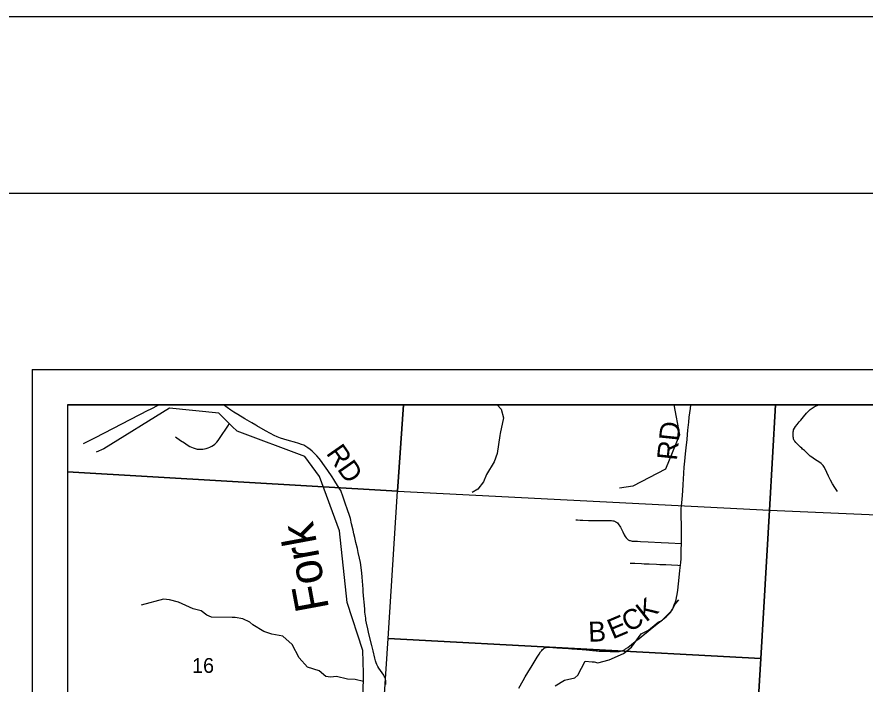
# Model space of a CAD drawing. Extents: x 21.4 to 65.3, y 4 to 26.
# Drawn here: x 23.404 to 25.81, y 24.062 to 25.954 of the extents above; entities that cross this region are included whole.
import ezdxf

# ---------------------------------------------------------------- set-up
doc = ezdxf.new("R2010")
doc.units = 0
for name, color, linetype in [('Default', 7, 'Continuous'), ('GM_X_County_Road', 7, 'Continuous'), ('GM_X_County_Road_Text', 7, 'Continuous'), ('GM_X_Minor_River', 7, 'Continuous'), ('GM_X_Minor_River_Text', 7, 'Continuous'), ('GM_X_Section', 7, 'Continuous'), ('GM_X_Section_Text', 7, 'Continuous'), ('GM_X_Township_Road', 7, 'Continuous'), ('GM_X_Township_Road_Text', 7, 'Continuous'), ('SH_Border', 7, 'Continuous'), ('SH_Cut_Line', 7, 'Continuous'), ('SH_Data', 7, 'Continuous')]:
    doc.layers.add(name, color=color, linetype=linetype)

msp = doc.modelspace()

# ---------------------------------------------------------------- linework, layer by layer
at = {"layer": 'Default'}
for points in [[(24.5002, 24.8542), (23.5473, 24.8542), (23.5473, 24.6641), (24.4839, 24.6087)], [(25.5568, 24.8542), (24.5002, 24.8542), (24.4839, 24.6087), (25.5389, 24.555)], [(26.6018, 24.8542), (25.5568, 24.8542), (25.5389, 24.555), (26.5825, 24.5101)], [(23.5473, 24.6641), (23.5473, 23.6293), (23.8211, 23.6164), (24.4175, 23.5863), (24.4178, 23.5899), (24.4301, 23.7749), (24.457, 24.1912), (24.4839, 24.6087)]]:
    msp.add_lwpolyline(points, close=True, dxfattribs=at)
msp.add_lwpolyline([(26.3906, 21.3613), (26.4573, 22.45), (26.4915, 22.9722), (26.4968, 23.0532), (26.5076, 23.2181), (26.5201, 23.4302), (26.5253, 23.5099), (26.571, 24.2838), (26.5714, 24.2916), (26.5716, 24.3007), (26.5721, 24.3116), (26.5728, 24.3278), (26.5729, 24.3421), (26.5729, 24.3464), (26.5731, 24.3575), (26.5731, 24.358), (26.5731, 24.3616), (26.5731, 24.3659), (26.5732, 24.3694), (26.5734, 24.3737), (26.5741, 24.3781), (26.6018, 24.8542), (23.5473, 24.8542), (23.5473, 20.5568)], dxfattribs=at)
at = {"layer": 'GM_X_County_Road'}
msp.add_lwpolyline([(24.4506, 24.0605), (24.4504, 24.071), (24.45, 24.0737), (24.4494, 24.0764), (24.4485, 24.0791), (24.4476, 24.0811), (24.4459, 24.0845), (24.4444, 24.0874), (24.4403, 24.094), (24.4355, 24.1006), (24.4311, 24.1066), (24.4278, 24.1117), (24.425, 24.1172), (24.4229, 24.1223), (24.4209, 24.1281), (24.419, 24.1353), (24.4145, 24.1565), (24.4128, 24.1638), (24.411, 24.1717), (24.4027, 24.2042), (24.3993, 24.2181), (24.3957, 24.235), (24.3942, 24.2429), (24.3934, 24.2484), (24.3913, 24.2663), (24.3908, 24.2731), (24.3897, 24.286), (24.3876, 24.312), (24.3865, 24.3243), (24.386, 24.3304), (24.385, 24.343), (24.3843, 24.3528), (24.3834, 24.3658), (24.3825, 24.3764), (24.3806, 24.3925), (24.3784, 24.4066), (24.376, 24.4194), (24.3724, 24.4352), (24.3699, 24.4461), (24.3658, 24.463), (24.3624, 24.4775), (24.3601, 24.4878), (24.3577, 24.4981), (24.3535, 24.5163), (24.3498, 24.5314), (24.3472, 24.5403), (24.342, 24.5557), (24.3354, 24.575), (24.328, 24.5975), (24.325, 24.6057), (24.3225, 24.6107), (24.3204, 24.6146), (24.3157, 24.6226), (24.3089, 24.6331), (24.303, 24.6419), (24.2979, 24.6496), (24.2857, 24.6677), (24.2719, 24.6875), (24.2676, 24.6936), (24.2615, 24.7015), (24.2549, 24.709), (24.2489, 24.7153), (24.2417, 24.7223), (24.2356, 24.7276), (24.2296, 24.7321), (24.2238, 24.7359), (24.2176, 24.7391), (24.2113, 24.7417), (24.2036, 24.7443), (24.191, 24.748), (24.1772, 24.7518), (24.1611, 24.7565), (24.1512, 24.7598), (24.1425, 24.7631), (24.1335, 24.7672), (24.123, 24.7725), (24.109, 24.7804), (24.0844, 24.7946), (24.0815, 24.7962), (24.0702, 24.8027), (24.0499, 24.8147), (24.0301, 24.8264), (24.0191, 24.8333), (24.0108, 24.8388), (24.0007, 24.846), (23.9924, 24.8524), (23.9903, 24.8542)], dxfattribs=at)
at = {"layer": 'GM_X_Minor_River'}
for points in [[(24.521, 23.3563), (24.5022, 23.4691), (24.5165, 23.5341), (24.5149, 23.6613), (24.4719, 23.7265), (24.4054, 23.7901), (24.406, 23.8584), (24.3844, 23.9087), (24.3873, 24.0927), (24.385, 24.1568), (24.3406, 24.2931), (24.319, 24.497), (24.2627, 24.6502), (24.2202, 24.7075), (24.0286, 24.7795), (24.0144, 24.7922), (23.9767, 24.8306), (23.8365, 24.8445), (23.6501, 24.729), (23.6289, 24.7193)], [(24.7662, 24.8542), (24.7782, 24.842), (24.7842, 24.8169), (24.7747, 24.7724), (24.774, 24.7671), (24.7668, 24.7157), (24.758, 24.6918), (24.736, 24.6564), (24.7277, 24.6359), (24.7114, 24.6145), (24.6958, 24.605)], [(25.2681, 24.8542), (25.2842, 24.769), (25.2441, 24.6715), (25.1513, 24.6236), (25.1138, 24.6176)], [(24.387, 24.0692), (24.3632, 24.0744), (24.342, 24.0759), (24.3109, 24.0831), (24.2931, 24.0819), (24.2806, 24.0834), (24.2609, 24.0994), (24.2279, 24.11), (24.2048, 24.1366), (24.1847, 24.1745), (24.1582, 24.1977), (24.1267, 24.203), (24.1043, 24.2113), (24.0733, 24.2295), (24.0642, 24.2379), (24.0448, 24.2466), (24.0229, 24.2508), (24.0145, 24.2508), (23.9561, 24.2518), (23.9425, 24.2575), (23.9266, 24.2693), (23.9042, 24.2757), (23.8625, 24.2943), (23.8368, 24.3011), (23.8197, 24.3026), (23.7564, 24.2855)], [(24.9311, 24.0564), (24.958, 24.0731), (24.9872, 24.08), (24.9951, 24.0872), (25.016, 24.1272), (25.0361, 24.1249), (25.0414, 24.1245), (25.0524, 24.1223), (25.0842, 24.1303), (25.1248, 24.1482), (25.1479, 24.1668), (25.1756, 24.2041), (25.1957, 24.2148), (25.2238, 24.2376), (25.234, 24.2422), (25.2628, 24.2711), (25.2715, 24.2886), (25.2818, 24.3004)]]:
    msp.add_lwpolyline(points, dxfattribs=at)
at = {"layer": 'GM_X_Section'}
for points in [[(24.4839, 24.6087), (25.5389, 24.555), (25.5145, 24.1345), (24.457, 24.1912)], [(26.5825, 24.5101), (26.5198, 23.4854), (25.4788, 23.5287), (25.4893, 23.7114), (25.5145, 24.1345), (25.5389, 24.555)], [(25.5145, 24.1345), (25.4893, 23.7114), (24.4301, 23.7749), (24.457, 24.1912)]]:
    msp.add_lwpolyline(points, close=True, dxfattribs=at)
at = {"layer": 'GM_X_Township_Road'}
for points in [[(23.5926, 24.7441), (23.6269, 24.761), (23.7765, 24.8386), (23.7826, 24.8417), (23.8064, 24.8538), (23.8072, 24.8542)], [(25.2355, 24.2439), (25.2379, 24.2457), (25.2462, 24.2522), (25.2484, 24.2543), (25.252, 24.2578), (25.2549, 24.2609), (25.2581, 24.2646), (25.2613, 24.2694), (25.2637, 24.2745), (25.2656, 24.2784), (25.2691, 24.2867), (25.2723, 24.295), (25.2741, 24.3006), (25.2758, 24.3072), (25.2775, 24.3163), (25.2791, 24.328), (25.2812, 24.3459), (25.285, 24.3835), (25.286, 24.3921), (25.2865, 24.3983), (25.2874, 24.4077), (25.2882, 24.4161), (25.2886, 24.4223), (25.2888, 24.4291), (25.289, 24.4428), (25.2893, 24.4602), (25.2895, 24.4788), (25.2895, 24.4962), (25.2892, 24.5154), (25.2887, 24.5353), (25.2887, 24.5508), (25.289, 24.5595), (25.2895, 24.567), (25.2911, 24.5856), (25.2935, 24.6103), (25.2946, 24.6276), (25.2952, 24.6431), (25.297, 24.6769), (25.2986, 24.6943), (25.3009, 24.715), (25.3027, 24.7316), (25.3054, 24.7557), (25.3067, 24.7699), (25.3079, 24.7823), (25.3101, 24.8052), (25.3117, 24.8194), (25.3132, 24.8317), (25.3147, 24.8434), (25.3162, 24.8542)], [(25.7319, 24.608), (25.7282, 24.6135), (25.7245, 24.6193), (25.7184, 24.6298), (25.7124, 24.6406), (25.7069, 24.6512), (25.7016, 24.6623), (25.6956, 24.676), (25.6938, 24.6792), (25.692, 24.6817), (25.6891, 24.6849), (25.6863, 24.6873), (25.6822, 24.6902), (25.6675, 24.6994), (25.663, 24.7025), (25.6593, 24.7051), (25.6549, 24.7085), (25.6503, 24.7126), (25.6452, 24.7176), (25.6384, 24.724), (25.6357, 24.7265), (25.6334, 24.7286), (25.6311, 24.7308), (25.6276, 24.7343), (25.6176, 24.7435), (25.6137, 24.7474), (25.6109, 24.7508), (25.6096, 24.7529), (25.6086, 24.755), (25.6079, 24.7572), (25.6071, 24.7608), (25.6068, 24.763), (25.6064, 24.7666), (25.6062, 24.7703), (25.6061, 24.7739), (25.6064, 24.7772), (25.607, 24.7802), (25.6079, 24.7827), (25.6103, 24.7875), (25.6131, 24.7921), (25.6174, 24.798), (25.6236, 24.8057), (25.6279, 24.8109), (25.636, 24.8202), (25.6448, 24.83), (25.6512, 24.8367), (25.6552, 24.8405), (25.6606, 24.8448), (25.6659, 24.848), (25.6714, 24.8508), (25.6792, 24.8542)], [(23.8534, 24.763), (23.8682, 24.7531), (23.8787, 24.7459), (23.8865, 24.7408), (23.8945, 24.7359), (23.8989, 24.7335), (23.9036, 24.7316), (23.9096, 24.7298), (23.9152, 24.7286), (23.9202, 24.728), (23.9259, 24.7279), (23.9315, 24.7283), (23.9359, 24.7289), (23.9408, 24.73), (23.9462, 24.7316), (23.9514, 24.7337), (23.9565, 24.7363), (23.9613, 24.7393), (23.9653, 24.7423), (23.9682, 24.7448), (23.9712, 24.748), (23.9747, 24.7524), (23.9808, 24.7611), (24.0024, 24.7937), (24.007, 24.8008)], [(24.9894, 24.5282), (24.9944, 24.5276), (25.0018, 24.527), (25.0092, 24.5267), (25.0258, 24.526), (25.06, 24.5257), (25.071, 24.5257), (25.0908, 24.5255), (25.095, 24.5249), (25.0974, 24.5245), (25.0996, 24.5238), (25.1011, 24.5231), (25.1025, 24.5223), (25.1051, 24.5208), (25.1075, 24.5189), (25.1096, 24.5167), (25.1122, 24.5133), (25.1144, 24.51), (25.1165, 24.5067), (25.1185, 24.5029), (25.1228, 24.4939), (25.1272, 24.485), (25.13, 24.4801), (25.1322, 24.477), (25.1342, 24.4746), (25.1371, 24.472), (25.1387, 24.471), (25.1403, 24.47), (25.1421, 24.4693), (25.1439, 24.4687), (25.147, 24.468), (25.15, 24.4674), (25.1543, 24.4671), (25.1643, 24.4668), (25.1736, 24.4664), (25.1953, 24.4654), (25.2318, 24.4638), (25.2529, 24.4628), (25.2893, 24.4602)], [(25.1438, 24.4051), (25.1569, 24.4045), (25.1761, 24.4035), (25.1835, 24.4031), (25.1871, 24.403), (25.1902, 24.4029), (25.1926, 24.4029), (25.1982, 24.4028), (25.2186, 24.4021), (25.2285, 24.4014), (25.2453, 24.4006), (25.2608, 24.3999), (25.2793, 24.3988), (25.2865, 24.3983)], [(25.0669, 24.1553), (25.0708, 24.1552), (25.0758, 24.1551), (25.0808, 24.155), (25.0847, 24.1549), (25.0876, 24.1547), (25.1006, 24.154), (25.1074, 24.154), (25.1123, 24.1544), (25.1166, 24.1551), (25.1207, 24.1563), (25.1247, 24.158), (25.1274, 24.1593), (25.131, 24.1616), (25.137, 24.166), (25.1474, 24.1739), (25.1532, 24.1786), (25.1627, 24.1865), (25.169, 24.1916), (25.1807, 24.2009), (25.1939, 24.2112), (25.2002, 24.2163), (25.21, 24.2239), (25.2198, 24.2315), (25.2247, 24.2353), (25.2355, 24.2439)], [(24.8276, 24.0506), (24.84, 24.0721), (24.8463, 24.0828), (24.8536, 24.095), (24.8658, 24.1143), (24.8746, 24.1285), (24.8804, 24.138), (24.8823, 24.1412), (24.8859, 24.147), (24.8895, 24.1529), (24.8928, 24.1574), (24.8949, 24.1597), (24.8978, 24.1621), (24.9, 24.1635), (24.9022, 24.1646), (24.9051, 24.1655), (24.9088, 24.1661), (24.9132, 24.1664), (24.9184, 24.1662), (24.9249, 24.1656), (24.9362, 24.1649), (24.9515, 24.1639), (24.9583, 24.1634), (24.9781, 24.1621), (25.0078, 24.1597), (25.0189, 24.1587), (25.0285, 24.1577), (25.037, 24.1568), (25.0473, 24.156), (25.051, 24.1557), (25.056, 24.1555), (25.0669, 24.1553)]]:
    msp.add_lwpolyline(points, dxfattribs=at)
at = {"layer": 'SH_Border'}
msp.add_lwpolyline([(22.9473, 25.4542), (54.9473, 25.4542), (54.9473, 4.4542), (22.9473, 4.4542)], close=True, dxfattribs=at)
at = {"layer": 'SH_Cut_Line'}
msp.add_lwpolyline([(21.4473, 3.9542), (55.4473, 3.9542), (55.4473, 25.9542), (21.4473, 25.9542)], close=True, dxfattribs=at)
msp.add_lwpolyline([(29.9103, 24.8542), (23.5473, 24.8542), (23.5473, 18.0542)], dxfattribs=at)
at = {"layer": 'SH_Data'}
for p, q in [((23.4473, 24.9542), (30.4473, 24.9542)), ((23.4473, 24.9542), (23.4473, 17.9542)), ((23.5473, 24.8542), (23.5473, 18.0542)), ((23.5473, 24.8542), (30.3473, 24.8542))]:
    msp.add_line(p, q, dxfattribs=at)

# ---------------------------------------------------------------- texts
at = {"layer": 'GM_X_County_Road_Text'}
msp.add_text('RD', height=0.05682, rotation=304.9108, dxfattribs=at).set_placement((24.2795, 24.7165))
at = {"layer": 'GM_X_Minor_River_Text'}
msp.add_text('Fork', height=0.09468, rotation=100.5169, dxfattribs=at).set_placement((24.2897, 24.2764))
at = {"layer": 'GM_X_Section_Text'}
msp.add_text('16', height=0.04186, rotation=0, dxfattribs=at).set_placement((23.9007, 24.0937))
at = {"layer": 'GM_X_Township_Road_Text'}
for s, height, rotation, p in [('RD', 0.05682, 84.0946, (25.2763, 24.6947)), ('K', 0.0568, 38.4708, (25.1889, 24.2359)), ('C', 0.0568, 28.8789, (25.1394, 24.2076)), ('B', 0.0568, 2.069, (25.0259, 24.1817)), ('E', 0.0568, 22.8819, (25.0944, 24.1883))]:
    msp.add_text(s, height=height, rotation=rotation, dxfattribs=at).set_placement(p)

doc.saveas('drawing.dxf')
